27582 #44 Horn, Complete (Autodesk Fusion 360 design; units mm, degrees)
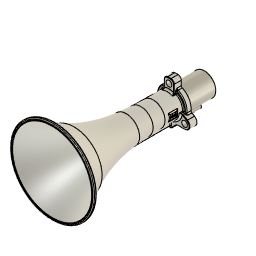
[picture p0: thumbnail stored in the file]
parameter "Bolt_Hole_Tolerance" = 1.5875 (= "( 1 / 16 ) * 1 in")
parameter "Dowel_Hole_Tolerance" = 0.0248 (= "( 1 / 1024 ) * 1 in")
canvas "Canvas1"
canvas "Canvas10"
sketch "Main Profile" plane through (0, 0, 0) normal (1, 0, 0) x axis (0, 1, 0)
  line L1 (0, -22.225) -> (0, 22.225)
  line L2 (-53.975, 22.225) -> (0, 22.225)
  line L3 (-53.975, 44.45) -> (-53.975, 22.225)
  line L4 (-294.4813, 0) -> (0, 0)
  line L5 (-68.2625, 44.45) -> (-53.975, 44.45)
  line L6 (-53.975, -22.225) -> (0, -22.225)
  line L7 (-53.975, 22.225) -> (-53.975, -22.225)
  line L8 (-53.975, -38.1) -> (-53.975, -22.225)
  line L9 (-68.2625, -38.1) -> (-53.975, -38.1)
  line L10 (-68.2625, 44.45) -> (-68.2625, -38.1)
  line L11 (-151.2832, 23.0187) -> (0, 11.1125)
  line L12 (-63.5, 28.575) -> (-53.975, 28.575)
  line L13 (-63.5, 19.2949) -> (-63.5, 28.575)
  line L14 (-151.0341, 26.184) -> (-63.5, 19.2949)
  line L15 (-294.4813, -80.9625) -> (-294.4812, 80.9625)
  line L16 (-68.2625, 19.6697) -> (-68.2625, 44.45)
  line L17 (9.1828, 34.925) -> (-68.2625, 34.925)
  line L18 (-34.1313, 22.225) -> (-34.1313, -22.225)
  line L19 (-68.2625, -18.1085) -> (-68.2625, -38.1)
  line L20 (-289.7188, 80.9625) -> (-294.4812, 80.9625)
  line L21 (-289.7188, 77.4158) -> (-289.7188, 80.9625)
  line L22 (-201.2383, -34.925) -> (-68.2625, -34.925)
  line L23 (-110.8163, 23.0187) -> (-68.2625, 23.0187)
  line L24 (-151.2832, 0) -> (-151.2832, 23.0187)
  line L25 (-151.2832, -23.0187) -> (0, -11.1125)
  line L26 (-289.7188, -77.4158) -> (-289.7187, -80.9625)
  line L27 (-289.7187, -80.9625) -> (-294.4812, -80.9625)
  line L28 (-110.8163, -23.0187) -> (-68.2625, -23.0188)
  line L29 (-151.0341, -26.184) -> (-63.5, -19.2949)
  line L30 (-63.5, 23.0188) -> (-68.2625, 23.0187)
  arc A1 centre (-98.8407, 327.8188) radius 304.8 clockwise from (-98.8407, 23.0187) to (-122.755, 23.9583)
  arc A2 centre (-129.6999, 297.2613) radius 275.0906 clockwise from (-151.2832, 23.0187) to (-294.4812, 76.9844)
  arc A3 centre (-129.6999, 297.2613) radius 271.9156 clockwise from (-151.0341, 26.184) to (-294.4812, 80.9625)
  arc A4 centre (-129.6999, -297.2613) radius 275.0906 clockwise from (-294.4812, -76.9844) to (-151.2832, -23.0187)
  arc A5 centre (-129.6999, -297.2613) radius 271.9156 clockwise from (-294.4812, -80.9625) to (-151.0341, -26.184)
  arc A6 centre (-98.8407, -327.8188) radius 304.8 clockwise from (-122.755, -23.9583) to (-98.8407, -23.0188)
  point P4 (0, 0)
  point P1 (0, 0)
  point P7 (0, 0)
  point P13 (0, 11.1125)
  point P15 (-53.975, 28.575)
  point P21 (-294.4813, 0)
  point P8 (-294.4813, 0)
  point P22 (-68.2625, 19.6697)
  point P23 (-68.2625, 34.925)
  point P25 (-34.1313, -22.225)
  point P26 (-34.1313, 22.225)
  point P27 (-68.2625, -18.1085)
  point P30 (-68.2625, -34.925)
  point P32 (-68.2625, 23.0187)
  point P33 (-110.8163, 23.0187)
  point P35 (-122.755, 23.9583)
  point P34 (-98.8407, 23.0187)
  point P37 (-294.4812, 76.9844)
  point P41 (-151.2832, 0)
  point P39 (-294.4812, 80.9625)
  point P29 (-289.7188, 77.4158)
  point P19 (-294.4812, 80.9625)
  point P42 (0, -11.1125)
  point P14 (-151.2832, 23.0187)
  point P43 (-151.2832, -23.0187)
  point P17 (-63.5, 19.2949)
  point P54 (-63.5, -19.2949)
  point P18 (-151.0341, 26.184)
  point P48 (-151.0341, -26.184)
  point P51 (-294.4812, -80.9625)
  point P28 (-289.7188, 80.9625)
  point P49 (-289.7187, -80.9625)
  point P50 (-289.7188, -77.4158)
  point P52 (-68.2625, -23.0188)
  point P53 (-110.8163, -23.0187)
  point P57 (-98.8407, -23.0188)
  point P56 (-122.755, -23.9583)
  point P45 (-294.4812, -76.9844)
  point P47 (-294.4812, -80.9625)
  point P31 (-201.2383, -34.925)
  point P58 (-63.5, 23.0188)
  point P2 (0, 22.225)
  point P5 (-53.975, 22.225)
  point P3 (0, -22.225)
  point P6 (-53.975, 44.45)
  point P9 (-68.2625, 44.45)
  point P16 (-63.5, 28.575)
  point P20 (-294.4813, -80.9625)
  point P12 (-68.2625, -38.1)
  vertical L1
  coincident L1 P4
  coincident P1 P4
  midpoint P1 L1
  perpendicular L1 L2
  perpendicular L2 L3
  coincident P1 P7
  perpendicular L1 L4
  perpendicular L3 L5
  perpendicular L1 L6
  vertical L7
  perpendicular L6 L8
  perpendicular L8 L9
  vertical L10
  coincident L1 P13
  coincident L3 P15
  perpendicular L3 L12
  perpendicular L12 L13
  parallel L11 L14
  vertical L15
  midpoint L15 P21
  coincident P8 P21
  coincident L14 P22
  coincident L10 P22
  coincident L10 P23
  perpendicular L16 L17
  coincident L6 P25
  coincident L2 P26
  perpendicular L2 L18
  coincident L10 P27
  perpendicular L9 L19
  perpendicular L15 L20
  vertical L21
  coincident L10 P30
  perpendicular L19 L22
  coincident L10 P32
  coincident L14 P33
  horizontal L23
  coincident L14 P35
  coincident L23 P34
  tangent L14 A1
  tangent L23 A1
  coincident L15 P37
  tangent L11 A2
  tangent L14 A3
  concentric A2 A3
  coincident L4 P41
  perpendicular L4 L24
  coincident L15 P39
  coincident P29 A3
  coincident P19 P39
  symmetric L4 P13 P42
  symmetric L4 P14 P43
  symmetric L4 P17 P54
  symmetric L4 P18 P48
  symmetric L4 P19 P51
  symmetric L4 P28 P49
  symmetric L4 P29 P50
  symmetric L4 P32 P52
  symmetric L4 P33 P53
  symmetric L4 P34 P57
  symmetric L4 P35 P56
  symmetric L4 A1 A6
  symmetric L4 P37 P45
  symmetric L4 A2 A4
  symmetric L4 P39 P47
  symmetric L4 A3 A5
  coincident P31 A5
  coincident L13 P58
  perpendicular L13 L30
  dimension "d1" distance P2 P5 = 53.975 (= "2 1/8")
  dimension "d2" distance P2 P3 = 44.45 (= "1 3/4")
  dimension "d3" distance P6 L4 = 44.45 (= "1 3/4")
  dimension "d4" distance P6 P9 = 14.2875 (= "( 9 / 16 ) * 1 in")
  dimension "d5" distance L4 L9 = 38.1
  dimension "d6" distance P4 P13 = 11.1125 (= "( 7 / 16 ) * 1 in")
  dimension "d7" distance L11 L14 = 3.175 (= "( 1 / 8 ) * 1 in")
  dimension "d9" distance P15 P16 = 9.525 (= "( 3 / 8 ) * 1 in")
  dimension "d10" distance L4 L12 = 28.575
  dimension "d11" distance L4 L17 = 34.925 (= "1 3/8")
  dimension "d12" distance P19 P20 = 161.925 (= "6 3/8")
  dimension "d17" distance L1 L18 = 34.1313 (= "1 11/32")
  dimension "d68" distance P19 P28 = 4.7625 (= "( 3 / 16 ) * 1 in")
  dimension "d157" distance L15 L18 = 260.35 (= "10 1/4")
  dimension "d175" distance P12 P30 = 3.175 (= "( 1 / 8 ) * 1 in")
  dimension "d197" angle L4 L11 = 4.5
  dimension "d198" distance L4 L23 = 23.0187 (= "( 29 / 32 ) * 1 in")
  dimension "d199" radius A1 = 304.8
  dimension "d201" distance P14 P41 = 23.0187 (= "( 29 / 32 ) * 1 in")
revolve "Revolve1" sketch "Main Profile" AlongAngle 360
revolve "Revolve3" sketch "Main Profile" AlongAngle 360
fillet "Fillet16" radius 158.75
sketch "Flange Profile" plane through (0, -53.975, 0) normal (0, 1, 0) x axis (-1, 0, 0)
  line L1 (0, 34.925) -> (0, 0)
  line L2 (0, 44.45) -> (0, 34.925)
  line L3 (3.175, 44.45) -> (-3.175, 44.45)
  line L4 (9.525, 31.1085) -> (9.525, 38.1)
  line L5 (-30.2459, -17.4625) -> (0, 0)
  line L6 (30.2459, -17.4625) -> (0, 0)
  line L7 (30.2459, -26.9875) -> (15.0812, -26.9875)
  line L8 (29.9633, -6.3008) -> (35.0084, -9.2136)
  line L9 (0, -31.75) -> (0, 0)
  line L10 (0, -38.1) -> (0, -31.75)
  line L11 (3.9688, -38.1) -> (-3.9688, -38.1)
  line L12 (15.0812, -26.9875) -> (3.9688, -38.1)
  line L13 (-15.0812, -26.9875) -> (-3.9688, -38.1)
  line L14 (-30.2459, -26.9875) -> (-15.0812, -26.9875)
  line L15 (-29.9633, -6.3008) -> (-35.0084, -9.2136)
  line L16 (-9.525, 31.1085) -> (-9.525, 38.1)
  line L17 (9.525, 20.0805) -> (9.525, 31.1085)
  line L18 (-9.525, 20.0805) -> (-9.525, 31.1085)
  line L19 (22.1527, -1.7913) -> (29.9633, -6.3008)
  line L20 (-22.1527, -1.7913) -> (-29.9633, -6.3008)
  circle C1 centre (0, 0) radius 22.225
  circle C2 centre (0, 34.925) radius 5.5563
  arc A1 centre (3.175, 38.1) radius 6.35 clockwise from (3.175, 44.45) to (9.525, 38.1)
  arc A2 centre (15.875, 31.1085) radius 6.35 clockwise from (12.9886, 25.4524) to (9.525, 31.1085)
  arc A3 centre (0, 0) radius 28.575 clockwise from (12.9886, 25.4524) to (28.3957, -3.196)
  circle C3 centre (-30.2459, -17.4625) radius 5.5563
  circle C4 centre (30.2459, -17.4625) radius 5.5563
  arc A4 centre (30.2459, -17.4625) radius 9.525 clockwise from (35.0084, -9.2136) to (30.2459, -26.9875)
  arc A5 centre (31.5508, -3.5512) radius 3.175 clockwise from (29.9633, -6.3008) to (28.3957, -3.196)
  circle C5 centre (0, -31.75) radius 3.9688
  arc A6 centre (-30.2459, -17.4625) radius 9.525 clockwise from (-30.2459, -26.9875) to (-35.0084, -9.2136)
  arc A7 centre (-31.5508, -3.5512) radius 3.175 clockwise from (-28.3957, -3.196) to (-29.9633, -6.3008)
  arc A8 centre (0, 0) radius 28.575 clockwise from (-28.3957, -3.196) to (-12.9886, 25.4524)
  arc A9 centre (-15.875, 31.1085) radius 6.35 clockwise from (-9.525, 31.1085) to (-12.9886, 25.4524)
  arc A10 centre (-3.175, 38.1) radius 6.35 clockwise from (-9.525, 38.1) to (-3.175, 44.45)
  circle C6 centre (0, 0) radius 28.575
  point P1 (0, 0)
  point P3 (0, 0)
  point P4 (0, 34.925)
  point P5 (0, 34.925)
  point P6 (0, 34.925)
  point P10 (0, 44.45)
  point P7 (0, 44.45)
  point P30 (0, 0)
  point P31 (0, -31.75)
  point P32 (0, -31.75)
  point P33 (0, -31.75)
  point P37 (0, -38.1)
  point P34 (0, -38.1)
  point P9 (3.175, 44.45)
  point P52 (-3.175, 44.45)
  point P11 (9.525, 38.1)
  point P50 (-9.525, 38.1)
  point P13 (9.525, 31.1085)
  point P49 (-9.525, 31.1085)
  point P14 (12.9886, 25.4524)
  point P47 (-12.9886, 25.4524)
  point P16 (28.3957, -3.196)
  point P45 (-28.3957, -3.196)
  point P24 (15.0812, -26.9875)
  point P39 (-15.0812, -26.9875)
  point P25 (30.2459, -26.9875)
  point P40 (-30.2459, -26.9875)
  point P26 (35.0084, -9.2136)
  point P42 (-35.0084, -9.2136)
  point P28 (29.9633, -6.3008)
  point P43 (-29.9633, -6.3008)
  point P36 (3.9688, -38.1)
  point P38 (-3.9688, -38.1)
  point P53 (9.525, 20.0805)
  point P54 (-9.525, 20.0805)
  point P55 (22.1527, -1.7913)
  point P56 (-22.1527, -1.7913)
  point P35 (-3.9688, -38.1)
  point P19 (0, 0)
  coincident P1 P3
  vertical L1
  coincident P4 P5
  coincident P5 P6
  parallel L1 L2
  horizontal L3
  coincident L3 P10
  midpoint L3 P10
  coincident P7 P10
  tangent L3 A1
  vertical L4
  tangent A1 L4
  tangent L4 A2
  tangent A2 A3
  concentric C1 A3
  horizontal L7
  tangent L7 A4
  concentric C4 A4
  tangent A4 L8
  tangent L8 A5
  tangent A3 A5
  coincident P1 P30
  vertical L9
  coincident P31 P32
  coincident P32 P33
  parallel L9 L10
  horizontal L11
  midpoint L11 P37
  coincident P34 P37
  symmetric L1 P9 P52
  symmetric L1 P11 P50
  symmetric L1 A1 A10
  symmetric L1 P13 P49
  symmetric L1 P14 P47
  symmetric L1 A2 A9
  symmetric L1 P16 P45
  symmetric L1 A3 A8
  symmetric L1 P24 P39
  symmetric L1 P25 P40
  symmetric L1 P26 P42
  symmetric L1 A4 A6
  symmetric L1 P28 P43
  symmetric L1 A5 A7
  symmetric L1 P36 P38
  coincident C1 P53
  tangent A2 L17
  tangent A9 L18
  coincident C1 P54
  coincident C1 P55
  tangent A5 L19
  coincident C1 P56
  tangent A7 L20
  dimension "d95" distance P3 P4 = 34.925 (= "1 3/8")
  dimension "d96" diameter C2 = 11.1125 (= "( 3 / 8 ) * 1 in + Bolt_Hole_Tolerance")
  dimension "d97" radius A1 = 6.35 (= "( 1 / 4 ) * 1 in")
  dimension "d98" distance P1 L3 = 44.45 (= "1 3/4")
  dimension "d99" distance P5 L4 = 9.525 (= "( 3 / 8 ) * 1 in")
  dimension "d100" radius A2 = 6.35 (= "( 1 / 4 ) * 1 in")
  dimension "d101" radius A3 = 28.575 (= "1 1/8")
  dimension "d104" radius A4 = 9.525 (= "( 3 / 8 ) * 1 in")
  dimension "d105" angle L7 L8 = 30
  dimension "d106" radius A5 = 3.175 (= "( 1 / 8 ) * 1 in")
  dimension "d107" distance P30 P31 = 31.75 (= "1 1/4")
  dimension "d108" diameter C5 = 7.9375 (= "( 5 / 16 ) * 1 in")
  dimension "d109" distance P35 P36 = 7.9375 (= "( 5 / 16 ) * 1 in")
  dimension "d110" angle L7 L12 = 135
  dimension "d111" distance P19 L11 = 38.1 (= "1 1/2")
  dimension "d103" C-Pattern1-Angle = 360
extrude "Extrude2" add sketch "Flange Profile" profile of C1 C2 L3 A1 L4 C3 C4 L7 A4 L8 C5 L11 L12 L13 L14 A6 L15 L16 A10 L17 L18 L19 L20 against normal blind 14.2875 (magnitude of "( -9 / 16 ) * 1 in")
extrude "Extrude6" add sketch "Main Profile" profile of L19 L22 along normal blind 3.175 (= "( 1 / 8 ) * 1 in")
mirror "Mirror5" mirrorStitchTolerance 0.1016
delete_face "DeleteFace14"
delete_face "DeleteFace15"
extrude "Extrude4" cut sketch "Flange Profile" profile of C2 C3 C4 against normal blind 14.3002
extrude "Extrude5" cut sketch "Flange Profile" profile of C5 against normal blind 9.525 (magnitude of "( -3 / 8 ) * 1 in")
fillet "Fillet27" radius 3.175 (= "( 1 / 8 ) * 1 in")
fillet "Fillet28" radius 1.5875 (= "( 1 / 16 ) * 1 in")
fillet "Fillet29" radius 25.4
fillet "Fillet30" radius 1.5875 (= "( 1 / 16 ) * 1 in")
fillet "Fillet31" radius 0.7937 (= "( 1 / 32 ) * 1 in")
sketch "Main Profile" plane through (0, -63.5, 0) normal (0, 1, 0) x axis (-1, 0, 0)
  circle C1 centre (0, -31.75) radius 3.9687
  circle C2 centre (0, -31.75) radius 3.175
  concentric C1 C2
  dimension "d137" diameter C2 = 6.35 (= "( 1 / 4 ) * 1 in")
extrude "Extrude1" new body sketch "Main Profile" along normal blind 53.975 (= "2 1/8") bodies "27281 Orifice Pin #5"
offset_faces "OffsetFaces1"
work_plane "WorkPlane1" RotateAngle -180
sketch "Orifice & Number Profile" plane through (0, -43.2509, -35.7188) normal (0, 0, -1) x axis (1, 0, 0)
  line L1 (3.9688, -33.7259) -> (-3.9687, -33.7259)
  line L2 (3.9688, 20.2491) -> (-3.9687, 20.2491)
  line L3 (0, 20.2491) -> (0, -33.7259)
  line L4 (-22.225, -43.2509) -> (22.225, -43.2509)
  line L5 (1.5875, -9.1196) -> (1.5875, -33.7259)
  line L6 (0, -9.1196) -> (1.5875, -9.1196)
  circle C1 centre (0, -9.1196) radius 0.9922
  point P6 (0, -33.7259)
  point P7 (0, 20.2491)
  point P8 (0, -9.1196)
  point P11 (1.5875, -33.7259)
  point P13 (0, -9.1196)
  point P12 (1.5875, -9.1196)
  midpoint L1 P6
  midpoint L2 P7
  coincident L3 P8
  coincident L1 P11
  perpendicular L1 L5
  coincident L3 P13
  perpendicular L3 L6
  coincident P8 P13
  dimension "d143" diameter C1 = 1.9844 (= "( 5 / 64 ) * 1 in")
  dimension "d144" distance P8 L4 = 34.1313
  dimension "d145" distance P12 P13 = 1.5875 (= "( 1 / 16 ) * 1 in")
  dimension "d146" Text1-Height = 3.175 (= "( 1 / 8 ) * 1 in")
emboss "Emboss1" sketch "Orifice & Number Profile" Depth -0.1984 (= "( -1 / 128 ) * 1 in") Horizontal Distance 0 Vertical Distance 0 Rotation Angle 0
extrude "Extrude2" cut sketch "Orifice & Number Profile" profile of C1 against normal blind 3.175 (magnitude of "( -1 / 8 ) * 1 in")
fillet "Fillet32" radius 1.5875 (= "( 1 / 16 ) * 1 in")
sketch "Branding Profile 1" plane through (0, 0, 0) normal (0, 0, 1) x axis (1, 0, 0)
  line L1 (-4.4552, -98.8407) -> (-4.4552, -71.4375)
  line L2 (-23.0187, -98.8407) -> (23.0187, -98.8407)
  line L3 (4.4552, -71.4375) -> (4.4552, -98.8407)
  line L4 (4.4552, -71.4375) -> (22.9839, -71.4375)
  line L5 (22.9839, -65.0875) -> (22.9839, -71.4375)
  line L6 (10.3956, -65.0875) -> (23.0187, -65.0875)
  line L7 (10.3956, -71.4375) -> (10.3956, -65.0875)
  line L8 (-10.3956, -71.4375) -> (10.3956, -71.4375)
  line L9 (-10.3956, -65.0875) -> (-10.3956, -71.4375)
  line L10 (-23.0187, -65.0875) -> (-10.3956, -65.0875)
  line L11 (-22.9839, -71.4375) -> (-22.9839, -65.0875)
  line L12 (-22.9839, -71.4375) -> (-4.4552, -71.4375)
  curve K1 (-4.4552, -98.8407) -> (-4.4674, -122.755)
  line L13 (-23.9583, -122.755) -> (23.9583, -122.755)
  curve K2 (4.4674, -122.755) -> (4.4552, -98.8407)
  line L14 (-23.0187, -98.8407) -> (23.0187, -98.8407)
  curve K3 (-4.4674, -122.755) -> (-4.4911, -151.0341)
  line L15 (-26.184, -151.0341) -> (26.184, -151.0341)
  curve K4 (4.4911, -151.0341) -> (4.4674, -122.755)
  line L16 (-23.9583, -122.755) -> (23.9583, -122.755)
  line L17 (-23.0187, -71.4375) -> (-23.0187, -98.8407)
  line L18 (-23.2172, -76.198) -> (-21.4313, -76.2164)
  line L19 (-23.61, -114.2959) -> (-23.2172, -76.198)
  line L20 (-21.8242, -114.3143) -> (-23.61, -114.2959)
  line L21 (-21.4313, -76.2164) -> (-21.8242, -114.3143)
  line L22 (-25.7527, -68.2625) -> (-34.6116, -68.2625)
  curve K5 (-3.7987, -198.2249) -> (-1.6578, -205.0098)
  curve K6 (-1.6578, -205.0098) -> (1.6578, -205.0098)
  curve K7 (1.6578, -205.0098) -> (3.7987, -198.2249)
  curve K8 (3.7987, -198.2249) -> (4.1866, -196.1324)
  curve K9 (4.1866, -196.1324) -> (4.5436, -190.0525)
  curve K10 (4.5436, -190.0525) -> (4.4911, -151.0341)
  line L23 (-26.184, -151.0341) -> (26.184, -151.0341)
  curve K11 (-4.4911, -151.0341) -> (-4.5436, -190.0525)
  curve K12 (-4.5436, -190.0525) -> (-4.1866, -196.1324)
  curve K13 (-4.1866, -196.1324) -> (-3.7987, -198.2249)
  line L24 (-54.1972, -251.593) -> (54.1973, -251.593)
  line L25 (-24.4881, -126.9655) -> (-22.9137, -127.1692)
  line L26 (-33.0436, -193.0893) -> (-24.4881, -126.9655)
  line L27 (-31.4693, -193.2931) -> (-33.0436, -193.0893)
  line L28 (-22.9137, -127.1692) -> (-31.4693, -193.2931)
  line L29 (21.4313, -76.2) -> (23.4156, -76.2)
  line L30 (21.4313, -88.9) -> (21.4313, -76.2)
  line L31 (23.4156, -88.9) -> (21.4313, -88.9)
  line L32 (23.4156, -76.2) -> (23.4156, -88.9)
  line L33 (0, 50.8) -> (0, 0)
  line L34 (23.0187, -71.4375) -> (23.0187, -98.8407)
  line L35 (34.6116, -68.2625) -> (25.7527, -68.2625)
  arc A1 centre (-328.7305, -98.8049) radius 305.7118 clockwise from (-23.0187, -98.8407) to (-23.9583, -122.755)
  arc A2 centre (-120688.9011, 9359.5543) radius 121036.9472 clockwise from (-23.9583, -122.755) to (-26.184, -151.0341)
  arc A3 centre (-297.4217, -129.6553) radius 272.079 clockwise from (-26.184, -151.0341) to (-54.1972, -251.593)
  arc A4 centre (297.4217, -129.6553) radius 272.079 clockwise from (54.1972, -251.593) to (26.184, -151.0341)
  arc A5 centre (120688.9011, 9359.5543) radius 121036.9472 clockwise from (26.184, -151.0341) to (23.9583, -122.755)
  arc A6 centre (328.7305, -98.8049) radius 305.7118 clockwise from (23.9583, -122.755) to (23.0187, -98.8407)
  point P25 (-23.0187, -98.8407)
  point P34 (-23.0187, -98.8407)
  point P35 (-23.0187, -71.4375)
  point P21 (-23.9583, -122.755)
  point P37 (-23.9583, -122.755)
  point P5 (-23.0187, -98.8407)
  point P36 (-23.0187, -98.8407)
  point P29 (-26.184, -151.0341)
  point P39 (-26.184, -151.0341)
  point P45 (-23.4116, -114.298)
  point P46 (-23.0187, -76.2)
  point P57 (-26.184, -151.0341)
  point P63 (-26.184, -151.0341)
  point P62 (-54.1972, -251.593)
  point P64 (-54.1972, -251.593)
  point P70 (-32.8468, -193.1148)
  point P71 (-24.2913, -126.991)
  point P1 (0, 0)
  point P76 (0, 0)
  point P86 (23.0187, -98.8407)
  point P87 (23.0187, -71.4375)
  point P85 (23.0187, -98.8407)
  point P83 (23.9583, -122.755)
  point P82 (26.184, -151.0341)
  point P80 (26.184, -151.0341)
  point P79 (54.1972, -251.593)
  point P88 (23.0187, -76.2)
  point P43 (-23.61, -114.2959)
  point P42 (-23.2172, -76.198)
  point P41 (-21.4313, -76.2164)
  point P67 (-24.4881, -126.9655)
  point P68 (-33.0436, -193.0893)
  point P66 (-22.9137, -127.1692)
  point P72 (23.4156, -76.2)
  point P75 (23.4156, -88.9)
  coincident P25 P34
  vertical L17
  coincident L12 P35
  tangent L17 A1
  coincident P21 P37
  coincident P5 P36
  coincident P29 P39
  tangent A1 A2
  perpendicular L18 L19
  perpendicular L19 L20
  perpendicular L20 L21
  coincident L20 P45
  coincident L18 P46
  coincident L17 P46
  coincident A1 P45
  coincident P57 P63
  coincident P62 P64
  tangent A2 A3
  perpendicular L25 L26
  perpendicular L26 L27
  perpendicular L27 L28
  coincident L27 P70
  coincident A3 P70
  coincident L25 P71
  coincident A2 P71
  perpendicular L29 L30
  perpendicular L30 L31
  perpendicular L31 L32
  coincident P1 P76
  vertical L33
  symmetric P34 L33 P86
  symmetric P35 L33 P87
  symmetric P36 L33 P85
  symmetric P37 L33 P83
  symmetric A1 L33 A6
  symmetric P39 L33 P82
  symmetric A2 L33 A5
  symmetric P63 L33 P80
  symmetric P64 L33 P79
  symmetric A3 L33 A4
  coincident L34 P88
  coincident L29 P88
  vertical L32
  dimension "d216" distance P46 L22 = 7.9375 (= "( 5 / 16 ) * 1 in")
  dimension "d217" distance P43 P45 = 0.1984 (= "( 1 / 128 ) * 1 in")
  dimension "d218" distance P42 P46 = 0.1984 (= "d217")
  dimension "d219" distance P41 P46 = 1.5875 (= "( 1 / 16 ) * 1 in")
  dimension "d238" distance P67 P71 = 0.1984 (= "( 1 / 128 ) * 1 in")
  dimension "d239" distance P68 P70 = 0.1984 (= "d238")
  dimension "d240" distance P66 P67 = 1.5875 (= "( 1 / 16 ) * 1 in")
  dimension "d241" distance P67 P68 = 66.675 (= "2 5/8")
  dimension "d242" distance P42 P43 = 38.1 (= "1 1/2")
  dimension "d243" distance P43 P67 = 12.7 (= "( 1 / 2 ) * 1 in")
  dimension "d260" distance P72 P88 = 0.3969 (= "( 1 / 64 ) * 1 in")
  dimension "d263" distance P88 L35 = 7.9375 (= "( 5 / 16 ) * 1 in")
  dimension "d264" distance P72 P75 = 12.7 (= "( 1 / 2 ) * 1 in")
extrude "Extrude10" add sketch "Branding Profile 1" profile of L2 L14 L17 A1 L18 L19 L20 L21 distance 19.05 (= "( 3 / 4 ) * 1 in")
delete_face "DeleteFace16"
sketch "Branding Profile 2" plane through (-22.4291, 0.2313, 0) normal (-0.9999, 0.0103, 0) x axis (-0.0103, -0.9999, 0)
  line L1 (114.5333, 9.525) -> (114.5333, -9.525)
  line L2 (76.4333, 9.525) -> (114.5333, 9.525)
  line L3 (76.4333, -9.525) -> (76.4333, 9.525)
  line L4 (114.5333, -9.525) -> (76.4333, -9.525)
  line L5 (94.6103, -1.131) -> (92.2224, 2.1371)
  line L6 (108.9955, -0.9686) -> (109.523, -0.9686)
  line L7 (102.3363, -4.8781) -> (102.3363, -5.6373)
  line L8 (96.0576, 3.3576) -> (96.0576, 4.8791)
  line L9 (89.0662, -0.4801) -> (89.0662, 0.0594)
  line L10 (90.6251, 4.8553) -> (90.6251, 5.2322)
  line L11 (92.1406, 2.3877) -> (92.1406, 4.8031)
  line L12 (95.663, 5.2738) -> (92.6113, 5.2738)
  line L13 (94.9004, -4.2813) -> (94.9004, -2.0198)
  line L14 (90.8546, -5.0959) -> (90.8546, -5.528)
  line L15 (87.7546, -4.4596) -> (87.7546, -1.4472)
  line L16 (96.4069, -5.0326) -> (96.4069, -1.5281)
  line L17 (82.916, -6.7702) -> (83.9845, -6.2258)
  line L18 (88.2381, -0.9636) -> (88.5827, -0.9636)
  line L19 (82.1503, -6.301) -> (82.1503, 7.809)
  line L20 (80.5158, -8.3956) -> (80.5158, 8.2084)
  line L21 (86.2481, -6.3626) -> (86.2481, 6.0597)
  line L22 (84.4791, -7.7782) -> (81.765, -9.1611)
  line L23 (90.4738, -6.0315) -> (87.0808, -6.9922)
  line L24 (93.1671, -4.2813) -> (93.1671, -2.0448)
  line L25 (84.8722, -6.7697) -> (84.8722, -7.1367)
  line L26 (108.6189, 0.9145) -> (108.6189, -1.3453)
  line L27 (109.8997, -0.592) -> (109.8997, 0.1613)
  line L28 (110.5811, 9.0165) -> (107.4447, 7.6922)
  line L29 (87.7546, 1.0264) -> (87.7546, 3.9726)
  line L30 (88.6243, 4.6563) -> (89.9593, 4.3319)
  line L31 (87.7546, 1.0264) -> (87.7546, -1.4472)
  line L32 (81.9484, 8.1969) -> (81.3281, 8.6312)
  line L33 (106.9844, -6.6138) -> (106.9844, 6.9982)
  line L34 (101.9127, -6.011) -> (98.5373, -5.5871)
  line L35 (105.2694, 6.3232) -> (105.2694, -6.3604)
  line L36 (96.1168, -0.6393) -> (93.5293, 2.9021)
  line L37 (99.7142, -4.2166) -> (102.0066, -4.5044)
  line L38 (103.7628, -6.1011) -> (103.7628, 6.0639)
  line L39 (92.7998, -5.4092) -> (96.0303, -5.4092)
  line L40 (94.5163, -4.6653) -> (93.5512, -4.6653)
  line L41 (108.6189, -5.948) -> (108.6189, -1.3453)
  line L42 (99.3844, -3.8429) -> (99.3844, 5.1103)
  line L43 (110.9782, -7.2726) -> (108.8384, -6.2903)
  line L44 (88.5917, -5.0926) -> (90.2349, -4.6273)
  line L45 (93.4458, 3.158) -> (93.4458, 3.5592)
  line L46 (107.4234, -7.2984) -> (110.6639, -8.7861)
  line L47 (104.7701, -6.7165) -> (104.0168, -6.4572)
  line L48 (90.2127, 5.7567) -> (86.8896, 6.5641)
  line L49 (97.8779, -4.8397) -> (97.8779, 5.1103)
  line L50 (111.1977, -8.4438) -> (111.1977, -7.6149)
  line L51 (92.4232, -2.0448) -> (92.4232, -5.0326)
  line L52 (92.7905, -1.6682) -> (92.7998, -1.6682)
  line L53 (94.775, 3.8359) -> (94.8682, 3.2617)
  line L54 (93.4458, 3.5592) -> (93.4458, 3.7743)
  line L55 (109.523, 0.5379) -> (108.9955, 0.5379)
  line L56 (111.1043, 7.8519) -> (111.1043, 8.6696)
  line L57 (108.849, 6.6498) -> (110.8742, 7.5049)
  line L58 (99.0078, 5.487) -> (98.2545, 5.487)
  line L59 (93.8298, 4.1584) -> (94.3959, 4.1584)
  line L60 (104.0168, 6.42) -> (104.7701, 6.6793)
  line L61 (108.6189, 0.9145) -> (108.6189, 6.3029)
  line L62 (88.5827, 0.5429) -> (88.2381, 0.5429)
  arc A1 centre (94.3959, 3.7743) radius 0.3841 clockwise from (94.3959, 4.1584) to (94.775, 3.8359)
  arc A2 centre (99.7611, -3.8429) radius 0.3766 clockwise from (99.7142, -4.2166) to (99.3844, -3.8429)
  arc A3 centre (110.8211, -7.6149) radius 0.3766 clockwise from (110.9782, -7.2726) to (111.1977, -7.6149)
  arc A4 centre (81.032, 8.2084) radius 0.5162 clockwise from (80.5158, 8.2084) to (81.3281, 8.6312)
  arc A5 centre (109.523, -0.592) radius 0.3766 clockwise from (109.8997, -0.592) to (109.523, -0.9686)
  arc A6 centre (88.4582, 3.9726) radius 0.7035 clockwise from (87.7546, 3.9726) to (88.6243, 4.6563)
  arc A7 centre (90.0853, 5.2322) radius 0.5398 clockwise from (90.2127, 5.7567) to (90.6251, 5.2322)
  arc A8 centre (95.663, 4.8791) radius 0.3947 clockwise from (95.663, 5.2738) to (96.0576, 4.8791)
  arc A9 centre (92.5654, 2.3877) radius 0.4248 clockwise from (92.2224, 2.1371) to (92.1406, 2.3877)
  arc A10 centre (92.7905, -2.0448) radius 0.3766 clockwise from (92.7905, -1.6682) to (93.1671, -2.0448)
  arc A11 centre (88.2381, -1.4472) radius 0.4835 clockwise from (87.7546, -1.4472) to (88.2381, -0.9636)
  arc A12 centre (92.7998, -5.0326) radius 0.3766 clockwise from (92.7998, -5.4092) to (92.4232, -5.0326)
  arc A13 centre (88.5827, -0.4801) radius 0.4835 clockwise from (89.0662, -0.4801) to (88.5827, -0.9636)
  arc A14 centre (81.375, -8.3956) radius 0.8592 clockwise from (81.765, -9.1611) to (80.5158, -8.3956)
  arc A15 centre (90.3676, -5.0959) radius 0.487 clockwise from (90.2349, -4.6273) to (90.8546, -5.0959)
  arc A16 centre (84.2617, -6.7697) radius 0.6105 clockwise from (83.9845, -6.2258) to (84.8722, -6.7697)
  arc A17 centre (93.3938, -2.0198) radius 1.5065 clockwise from (94.6103, -1.131) to (94.9004, -2.0198)
  arc A18 centre (82.6769, -6.301) radius 0.5266 clockwise from (82.916, -6.7702) to (82.1503, -6.301)
  arc A19 centre (94.9004, -1.5281) radius 1.5065 clockwise from (96.1168, -0.6393) to (96.4069, -1.5281)
  arc A20 centre (108.9955, 0.9145) radius 0.3766 clockwise from (108.9955, 0.5379) to (108.6189, 0.9145)
  arc A21 centre (108.9955, 6.3029) radius 0.3766 clockwise from (108.6189, 6.3029) to (108.849, 6.6498)
  arc A22 centre (98.2545, 5.1103) radius 0.3766 clockwise from (97.8779, 5.1103) to (98.2545, 5.487)
  arc A23 centre (104.1395, 6.0639) radius 0.3766 clockwise from (103.7628, 6.0639) to (104.0168, 6.42)
  arc A24 centre (88.2381, 1.0264) radius 0.4835 clockwise from (88.2381, 0.5429) to (87.7546, 1.0264)
  arc A25 centre (90.0865, 4.8553) radius 0.5386 clockwise from (90.6251, 4.8553) to (89.9593, 4.3319)
  arc A26 centre (93.8796, 3.158) radius 0.4338 clockwise from (93.5293, 2.9021) to (93.4458, 3.158)
  arc A27 centre (99.0078, 5.1103) radius 0.3766 clockwise from (99.0078, 5.487) to (99.3844, 5.1103)
  arc A28 centre (107.7377, -6.6138) radius 0.7533 clockwise from (107.4234, -7.2984) to (106.9844, -6.6138)
  arc A29 centre (101.9597, -5.6373) radius 0.3766 clockwise from (102.3363, -5.6373) to (101.9127, -6.011)
  arc A30 centre (108.9955, -1.3453) radius 0.3766 clockwise from (108.6189, -1.3453) to (108.9955, -0.9686)
  arc A31 centre (110.8211, -8.4438) radius 0.3766 clockwise from (111.1977, -8.4438) to (110.6639, -8.7861)
  arc A32 centre (88.5827, 0.0594) radius 0.4835 clockwise from (88.5827, 0.5429) to (89.0662, 0.0594)
  arc A33 centre (92.7998, -2.0448) radius 0.3766 clockwise from (92.4232, -2.0448) to (92.7998, -1.6682)
  arc A34 centre (96.0303, -5.0326) radius 0.3766 clockwise from (96.4069, -5.0326) to (96.0303, -5.4092)
  arc A35 centre (90.3312, -5.528) radius 0.5233 clockwise from (90.8546, -5.528) to (90.4738, -6.0315)
  arc A36 centre (104.8927, -6.3604) radius 0.3766 clockwise from (105.2694, -6.3604) to (104.7701, -6.7165)
  arc A37 centre (101.9597, -4.8781) radius 0.3766 clockwise from (102.0066, -4.5044) to (102.3363, -4.8781)
  arc A38 centre (88.4125, -4.4596) radius 0.6578 clockwise from (88.5917, -5.0926) to (87.7546, -4.4596)
  arc A39 centre (94.5163, -4.2813) radius 0.3841 clockwise from (94.9004, -4.2813) to (94.5163, -4.6653)
  arc A40 centre (93.5512, -4.2813) radius 0.3841 clockwise from (93.5512, -4.6653) to (93.1671, -4.2813)
  arc A41 centre (98.6312, -4.8397) radius 0.7533 clockwise from (98.5373, -5.5871) to (97.8779, -4.8397)
  arc A42 centre (81.6768, 7.809) radius 0.4736 clockwise from (81.9484, 8.1969) to (82.1503, 7.809)
  arc A43 centre (86.9025, -6.3626) radius 0.6544 clockwise from (87.0808, -6.9922) to (86.2481, -6.3626)
  arc A44 centre (92.6113, 4.8031) radius 0.4706 clockwise from (92.1406, 4.8031) to (92.6113, 5.2738)
  arc A45 centre (108.9955, -5.948) radius 0.3766 clockwise from (108.8384, -6.2903) to (108.6189, -5.948)
  arc A46 centre (84.1523, -7.1367) radius 0.7199 clockwise from (84.8722, -7.1367) to (84.4791, -7.7782)
  arc A47 centre (104.1395, -6.1011) radius 0.3766 clockwise from (104.0168, -6.4572) to (103.7628, -6.1011)
  arc A48 centre (93.8298, 3.7743) radius 0.3841 clockwise from (93.4458, 3.7743) to (93.8298, 4.1584)
  arc A49 centre (95.4591, 3.3576) radius 0.5986 clockwise from (96.0576, 3.3576) to (94.8682, 3.2617)
  arc A50 centre (104.8927, 6.3232) radius 0.3766 clockwise from (104.7701, 6.6793) to (105.2694, 6.3232)
  arc A51 centre (107.7377, 6.9982) radius 0.7533 clockwise from (106.9844, 6.9982) to (107.4447, 7.6922)
  arc A52 centre (110.7276, 7.8519) radius 0.3766 clockwise from (111.1043, 7.8519) to (110.8742, 7.5049)
  arc A53 centre (110.7276, 8.6696) radius 0.3766 clockwise from (110.5811, 9.0165) to (111.1043, 8.6696)
  arc A54 centre (109.523, 0.1613) radius 0.3766 clockwise from (109.523, 0.5379) to (109.8997, 0.1613)
  arc A55 centre (86.7671, 6.0597) radius 0.519 clockwise from (86.2481, 6.0597) to (86.8896, 6.5641)
  point P152 (82.1503, -6.301)
  point P158 (82.1503, -6.301)
  point P82 (99.3844, -3.8429)
  point P90 (99.3844, -3.8429)
  point P95 (109.8997, -0.2154)
  point P106 (106.9844, -6.6138)
  point P170 (106.9844, -6.6138)
  tangent A4 L20
  tangent A4 L32
  tangent L32 A42
  tangent L19 A42
  vertical L19
  tangent A14 L20
  tangent A14 L22
  tangent L22 A46
  vertical L25
  tangent L25 A46
  tangent A16 L25
  tangent L17 A16
  parallel L17 L22
  tangent L17 A18
  coincident P152 P158
  tangent L19 A18
  vertical L21
  tangent L21 A55
  tangent L48 A55
  tangent A7 L48
  tangent A7 L10
  vertical L10
  tangent L10 A25
  tangent A25 L30
  parallel L30 L48
  tangent A6 L30
  vertical L29
  tangent A6 L29
  tangent A24 L29
  tangent A24 L62
  horizontal L62
  tangent A32 L62
  tangent L9 A32
  vertical L9
  tangent L9 A13
  horizontal L18
  tangent A13 L18
  tangent A11 L18
  vertical L15
  tangent A11 L15
  vertical L31
  tangent L21 A43
  tangent L23 A43
  tangent L23 A35
  vertical L14
  tangent L14 A35
  tangent L14 A15
  tangent A15 L44
  tangent A38 L44
  tangent L15 A38
  parallel L23 L44
  horizontal L12
  tangent A8 L12
  vertical L8
  tangent A8 L8
  tangent L8 A49
  tangent A49 L53
  tangent A1 L53
  tangent A1 L59
  horizontal L59
  tangent A48 L59
  vertical L54
  tangent A48 L54
  tangent L12 A44
  vertical L11
  tangent L11 A44
  tangent L11 A9
  tangent L5 A9
  parallel L45 L54
  tangent A26 L45
  tangent A26 L36
  parallel L5 L36
  tangent A19 L36
  vertical L16
  tangent L16 A19
  tangent L5 A17
  tangent L13 A17
  vertical L13
  tangent L16 A34
  horizontal L39
  tangent A34 L39
  tangent A12 L39
  vertical L51
  tangent A12 L51
  tangent A33 L51
  horizontal L52
  tangent A33 L52
  tangent A10 L52
  vertical L24
  tangent A10 L24
  tangent L24 A40
  tangent L13 A39
  tangent L40 A40
  tangent A39 L40
  vertical L49
  tangent A22 L49
  horizontal L58
  tangent A22 L58
  tangent A27 L58
  vertical L42
  tangent A27 L42
  tangent A41 L49
  tangent L34 A41
  tangent A29 L34
  vertical L7
  tangent L7 A29
  tangent L7 A37
  tangent L37 A37
  parallel L34 L37
  tangent A2 L37
  coincident P82 P90
  tangent A2 L42
  vertical L38
  tangent L38 A47
  tangent L47 A47
  tangent A36 L47
  vertical L35
  tangent L35 A36
  tangent L35 A50
  tangent A50 L60
  tangent A23 L60
  tangent A23 L38
  tangent L33 A51
  tangent L28 A51
  tangent L28 A53
  tangent L56 A53
  vertical L56
  tangent L56 A52
  tangent L57 A52
  parallel L28 L57
  tangent A21 L57
  vertical L61
  tangent A21 L61
  tangent A20 L61
  horizontal L55
  tangent A20 L55
  tangent L55 A54
  vertical L27
  tangent L27 A54
  tangent A5 L27
  horizontal L6
  tangent L6 A5
  tangent L6 A30
  vertical L41
  tangent A30 L41
  vertical L26
  midpoint P95 L27
  tangent L41 A45
  tangent L43 A45
  tangent A3 L43
  vertical L50
  tangent A3 L50
  tangent A31 L50
  tangent A31 L46
  parallel L43 L46
  tangent A28 L46
  coincident P106 P170
  tangent A28 L33
  dimension "d357" angle L20 L32 = 55
  dimension "d359" angle L20 L22 = 63
  dimension "d367" angle L8 L53 = 9.219
  dimension "d371" radius A9 = 0.4248
  dimension "d384" distance L12 L59 = 1.1154
  dimension "d395" angle L38 L47 = 109
  dimension "d400" angle L38 L60 = 109
  dimension "d339" angle L43 L50 = 114.659
extrude "Extrude11" add sketch "Branding Profile 2" profile of A1 A2 L5 L6 A3 L7 A4 A5 A6 A7 A8 L8 L9 L10 L11 L12 A9 L13 A10 A11 A12 A13 L14 A14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 along a picked direction blind 0.3969 (= "( 1 / 64 ) * 1 in") taper -30
fillet "Fillet33" radius 6.35 (= "( 1 / 4 ) * 1 in")
fillet "Fillet34" radius 3.175 (= "( 1 / 8 ) * 1 in")
fillet "Fillet35" radius 0.7937 (= "( 1 / 32 ) * 1 in")
extrude "Extrude12" add sketch "Branding Profile 1" profile of L15 A2 L23 A3 L25 L26 L27 L28 distance 19.05 (= "( 3 / 4 ) * 1 in")
sketch "Branding Profile 3" plane through (-7.9277, 1.0257, 0) normal (-0.9917, 0.1283, 0) x axis (-0.1283, -0.9917, 0)
  line L1 (195.7332, 9.525) -> (195.7332, -9.525)
  line L2 (129.0582, 9.525) -> (195.7332, 9.525)
  line L3 (129.0582, -9.525) -> (129.0582, 9.525)
  line L4 (195.7332, -9.525) -> (129.0582, -9.525)
  line L5 (195.7332, -3.175) -> (129.0582, -3.175)
  line L6 (195.7332, 0) -> (129.0582, 0)
  line L7 (162.3567, -4.7625) -> (130.284, -4.7625)
  line L8 (162.3567, -5.9531) -> (162.3567, -4.7625)
  line L9 (130.284, -5.9531) -> (162.3567, -5.9531)
  line L10 (130.284, -4.7625) -> (130.284, -5.9531)
  line L11 (130.284, 0) -> (130.284, -4.7625)
  line L12 (162.3567, 0) -> (162.3567, -4.7625)
  point P6 (129.0582, -3.175)
  point P7 (195.7332, -3.175)
  point P8 (129.0582, 0)
  point P9 (195.7332, 0)
  point P14 (130.284, 0)
  point P15 (162.3567, 0)
  point P10 (130.284, -4.7625)
  point P13 (130.284, -5.9531)
  coincident L3 P6
  coincident L1 P7
  perpendicular L1 L5
  midpoint L3 P8
  midpoint L1 P9
  horizontal L7
  vertical L8
  horizontal L9
  vertical L10
  coincident L6 P14
  perpendicular L6 L11
  coincident L6 P15
  perpendicular L6 L12
  dimension "d247" distance L5 L6 = 3.175 (= "( 1 / 8 ) * 1 in")
  dimension "d248" distance P10 P13 = 1.1906 (= "( 3 / 64 ) * 1 in")
  dimension "d249" distance L5 L7 = 1.5875 (= "( 1 / 16 ) * 1 in")
  dimension "d246" Text1-Height = 9.525 (= "( 3 / 8 ) * 1 in")
delete_face "DeleteFace17"
extrude "Extrude13" add sketch "Branding Profile 3" profile of L7 L8 L9 L10 along normal blind 0.3969 (= "( 1 / 64 ) * 1 in") taper -25
fillet "Fillet36" radius 6.35 (= "( 1 / 4 ) * 1 in")
fillet "Fillet37" radius 6.35 (= "( 1 / 4 ) * 1 in")
fillet "Fillet38" radius 3.175 (= "( 1 / 8 ) * 1 in")
fillet "Fillet39" radius 0.7937 (= "( 1 / 32 ) * 1 in")
extrude "Extrude14" add sketch "Branding Profile 1" profile of L29 L30 L31 L32 L34 distance 9.525 (= "( 3 / 8 ) * 1 in")
sketch "Branding Profile 4" plane through (23.4156, 0, 0) normal (1, 0, 0) x axis (0, 1, 0)
  line L1 (-76.2, 4.7625) -> (-76.2, -4.7625)
  line L2 (-88.9, 4.7625) -> (-76.2, 4.7625)
  line L3 (-88.9, -4.7625) -> (-88.9, 4.7625)
  line L4 (-76.2, -4.7625) -> (-88.9, -4.7625)
  line L5 (-76.2, -3.175) -> (-88.9, -3.175)
  line L6 (-88.9, 0) -> (-76.2, 0)
  point P6 (-88.9, -3.175)
  point P7 (-76.2, -3.175)
  point P8 (-76.2, 0)
  point P9 (-88.9, 0)
  coincident L3 P6
  coincident L1 P7
  perpendicular L1 L5
  midpoint L1 P8
  midpoint L3 P9
  dimension "d269" distance L5 L6 = 3.175 (= "( 1 / 8 ) * 1 in")
  dimension "d268" Text1-Height = 9.525 (= "( 3 / 8 ) * 1 in")
extrude "Extrude15" add sketch "Branding Profile 4" along normal blind 0.3969 (= "( 1 / 64 ) * 1 in") taper -25
fillet "Fillet45" radius 6.35 (= "( 1 / 4 ) * 1 in")
fillet "Fillet46" radius 3.175 (= "( 1 / 8 ) * 1 in")
fillet "Fillet47" radius 0.7937 (= "( 1 / 32 ) * 1 in")
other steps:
create_component "CreateComponent1"
create_component "CreateComponent2"
named bodies: "27281 Orifice Pin #5", "27466 #44 Horn"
